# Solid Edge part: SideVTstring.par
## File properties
Author: harmonj5
Template: ansi part.par
Last saved by: harmonj5
Revision: 3
Application: Solid Edge
Accuracy: 0.990
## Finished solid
Body 1: solid body, 6 faces, 12 edges, 8 vertices.
  Faces by surface: plane 6
  Edges by curve: line 12
Bounding box of the edges (mm): 5.867 x 273.050 x 3.302, from (-63.3813, 0, 7.9179) to (-57.5139, 273.05, 11.2199).
Planar faces by outward normal: +x 1, +y 1, +z 1, -x 1, -y 1, -z 1
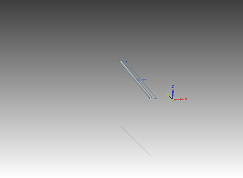
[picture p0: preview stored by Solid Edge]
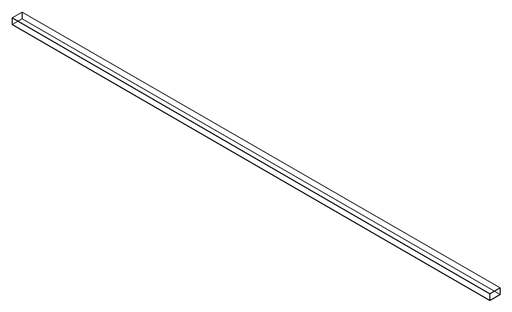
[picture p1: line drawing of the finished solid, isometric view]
